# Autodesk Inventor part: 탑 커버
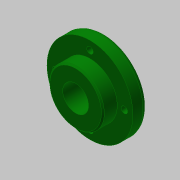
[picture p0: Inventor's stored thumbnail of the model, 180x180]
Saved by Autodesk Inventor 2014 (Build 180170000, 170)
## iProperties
Created: 2016-08
Part Number: 탑 커버
Material: 알루미늄 6061
Document SubType Name: Modeling
Designer: mduedu
Density: 2.71 g/cm^3
Appearance: Dark Green
Author: mduedu
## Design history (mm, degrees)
sketch "스케치1"
  geometry: L1 (0, 0)-(0, 10); L2 (0, 10)-(-30, 10); L3 (-30, 10)-(-30, 0); L4 (-30, 0)-(-19, 0); L5 (-19, 0)-(-19, -10); L6 (-19, -10)-(0, -10); L7 (0, -10)-(0, 10); 2 further points
  constraints: 14 end point, 3 parallel, 3 perpendicular, 1 coincident, 1 horizontal alignment, 1 midpoint, 1 vertical
  dimensions: "d0" = 10 distance of L1.start L1.end; "d2" = 60 diameter of L3 L1; "d3" = 38 diameter of L5 L1; "d4" = 20 distance between parallel lines of L6 L2
revolve "회전1" sketch "스케치1" stored, may be unused: angle "d5" = 90 deg
hole "구멍1" diameter "d8" = 18; stored, may be unused: countersink angle "d12" = 90 deg, drill point angle "d14" = 118 deg; dims "d6" = 10, "d7" = 10, "d9" = 6, "d10" = 4, "d11" = 2, "d13" = 8
chamfer "모따기1" distance "d15" = 1; stored, may be unused: second distance "d16" = 2, angle "d17" = 45 deg
chamfer "모따기2" distance "d18" = 1; stored, may be unused: second distance "d19" = 2, angle "d20" = 45 deg
fillet "모깎기1" dims "d21" = 3
sketch "스케치2" dims "d22" = 48
  geometry: 6 further points
  constraints: 2 vertical alignment, 1 coincident, 7 other
  dimensions: "d26" = 360 deg dimension on point (0, 0) point (0, 24) (derived)
sketch "스케치3"
  geometry: 4 further points
hole "구멍2" sketch "스케치3" at (-24, 0), (0, -24), (24, 0), (0, 24) diameter "d28" = 4.5; stored, may be unused: countersink angle "d32" = 90 deg, drill point angle "d34" = 0 deg; dims "d29" = 6, "d30" = 8, "d31" = 4.6, "d33" = 8
node "솔리드1"
